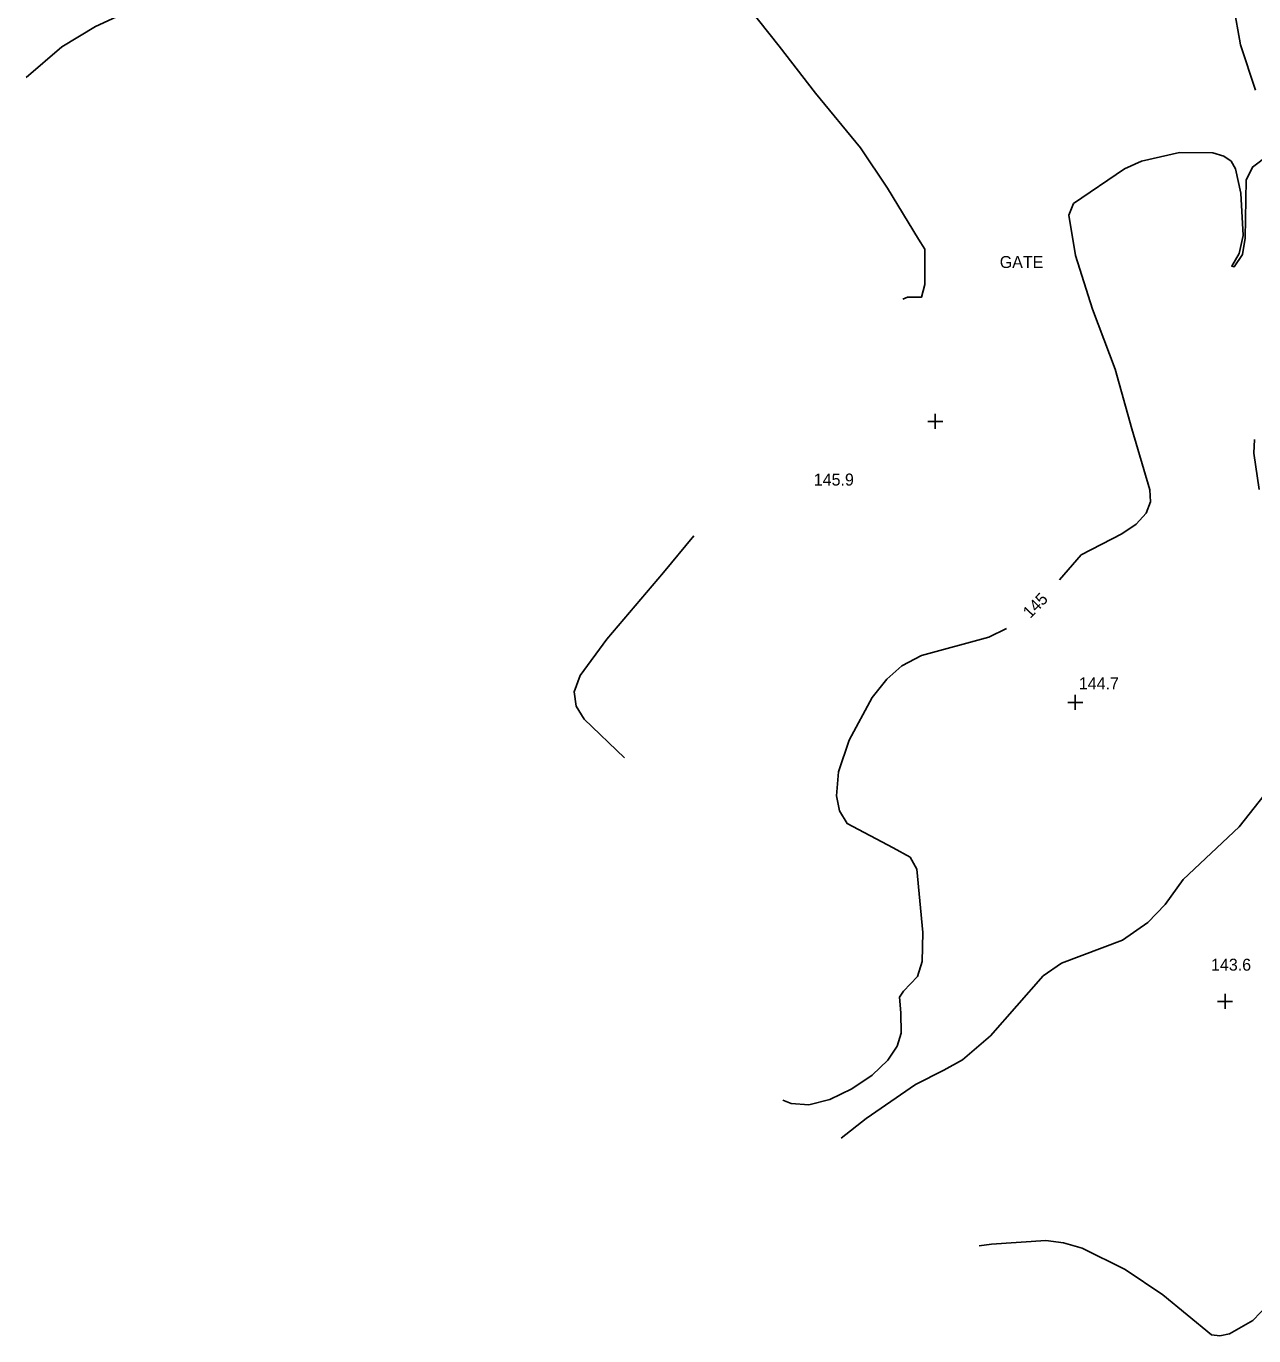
# Model space of a CAD drawing. Extents: x 1475150 to 2003689, y 770235 to 1112803.
# Drawn here: x 2000499.7 to 2000704.8, y 773169.2 to 773388 of the extents above; entities that cross this region are included whole.
import ezdxf

# ---------------------------------------------------------------- set-up
doc = ezdxf.new("R2010")
doc.units = 0
for name, color, linetype in [('RD_DTM_Major1', 7, 'Continuous'), ('RD_DTM_Major1_Lbl', 7, 'Continuous'), ('RD_DTM_Minor1', 7, 'Continuous'), ('RD_DTM_Spot_Elev', 7, 'Continuous'), ('RD_TX_Misc1', 7, 'Continuous')]:
    doc.layers.add(name, color=color, linetype=linetype)

msp = doc.modelspace()

# ---------------------------------------------------------------- linework, layer by layer
at = {"layer": 'RD_DTM_Major1'}
for points in [[(2000705.14, 773377.31), (2000702.59, 773384.88), (2000701.44, 773391.45), (2000701.5, 773391.94), (2000699.64, 773396.47), (2000696.55, 773402.64), (2000692.45, 773404.42), (2000684.77, 773413.19), (2000676.69, 773422.15), (2000669.9, 773431), (2000663.35, 773440.44), (2000659.41, 773446.84), (2000651.72, 773456.99), (2000645.49, 773466.43), (2000644.78, 773467.94), (2000651.37, 773460.88), (2000657.94, 773454.69), (2000665.19, 773448.22), (2000677.03, 773437.38), (2000688.27, 773427.04), (2000699.21, 773417.42), (2000702.1, 773418.42), (2000706.28, 773417.44)], [(2000672.38, 773295.48), (2000675.99, 773299.66), (2000682.8, 773303.17), (2000685.16, 773304.8), (2000686.87, 773306.6), (2000687.58, 773308.5), (2000687.46, 773310.53), (2000684.47, 773320.74), (2000681.69, 773330.68), (2000677.88, 773340.71), (2000675.03, 773349.68), (2000673.94, 773356.43), (2000674.71, 773358.35), (2000683.21, 773364.16), (2000686.05, 773365.46), (2000692.44, 773366.88), (2000697.99, 773366.81), (2000699.81, 773366.3), (2000701.03, 773365.43), (2000701.8, 773364.14), (2000702.68, 773360.09), (2000703.07, 773353.04), (2000702.39, 773350.01), (2000701.15, 773347.87), (2000701.57, 773347.79), (2000702.93, 773349.85), (2000703.37, 773352.6), (2000703.54, 773362.29), (2000704.61, 773364.46), (2000707.35, 773366.5)], [(2000626.16, 773208.53), (2000627.55, 773207.98), (2000630.51, 773207.78), (2000634, 773208.67), (2000637.67, 773210.43), (2000641.05, 773212.72), (2000643.68, 773215.2), (2000645.25, 773217.57), (2000645.92, 773219.73), (2000645.85, 773223.15), (2000645.65, 773225.78), (2000646.28, 773226.78), (2000648.65, 773229.19), (2000649.43, 773231.7), (2000649.53, 773236.55), (2000648.51, 773247.13), (2000647.43, 773249.12), (2000644.58, 773250.71), (2000636.89, 773254.76), (2000635.62, 773256.86), (2000635.09, 773259.4), (2000635.44, 773263.41), (2000637.24, 773268.67), (2000641.06, 773275.84), (2000643.5, 773278.89), (2000646.03, 773281.1), (2000649.29, 773282.82), (2000660.57, 773285.92), (2000663.53, 773287.35)]]:
    msp.add_lwpolyline(points, dxfattribs=at)
at = {"layer": 'RD_DTM_Minor1'}
for points in [[(2000499.72, 773379.42), (2000505.7, 773384.57), (2000511.32, 773387.93), (2000518.41, 773391.23)], [(2000646.18, 773342.38), (2000646.95, 773342.74), (2000649.33, 773342.73), (2000649.85, 773344.85), (2000649.87, 773350.73), (2000648.8, 773352.43), (2000643.61, 773360.94), (2000639.12, 773367.69), (2000631.63, 773376.83), (2000625.53, 773384.66), (2000620.36, 773391.16)], [(2000705.75, 773310.56), (2000704.82, 773316.67), (2000704.93, 773318.92)], [(2000599.69, 773265.74), (2000592.97, 773272.21), (2000591.59, 773274.39), (2000591.28, 773276.77), (2000592.26, 773279.49), (2000596.76, 773285.55), (2000606.22, 773296.7), (2000611.29, 773302.83)], [(2000635.87, 773202.2), (2000640.09, 773205.47), (2000648.3, 773211.17), (2000653.06, 773213.55), (2000656.17, 773215.26), (2000660.83, 773219.31), (2000669.67, 773229.29), (2000672.71, 773231.45), (2000682.89, 773235.25), (2000687.14, 773238.23), (2000690.05, 773241.26), (2000693.02, 773245.41), (2000702.38, 773254.19), (2000710.74, 773264.78)], [(2000658.94, 773184.22), (2000661.01, 773184.5), (2000670.11, 773185.08), (2000673.02, 773184.73), (2000676.18, 773183.83), (2000683.33, 773180.27), (2000689.66, 773176.01), (2000697.76, 773169.34), (2000699.15, 773169.17), (2000700.78, 773169.48), (2000704.69, 773171.74), (2000708.5, 773175.76)]]:
    msp.add_lwpolyline(points, dxfattribs=at)
at = {"layer": 'RD_DTM_Spot_Elev'}
for p, q in [((2000651.62, 773320.71), (2000651.62, 773323.21)), ((2000650.37, 773321.96), (2000652.87, 773321.96)), ((2000673.75, 773275), (2000676.25, 773275)), ((2000675, 773273.75), (2000675, 773276.25)), ((2000698.8, 773225.04), (2000701.3, 773225.04)), ((2000700.05, 773223.79), (2000700.05, 773226.29))]:
    msp.add_line(p, q, dxfattribs=at)

# ---------------------------------------------------------------- texts
at = {"layer": 'RD_DTM_Major1_Lbl'}
msp.add_text('145', height=2, rotation=45.6259, dxfattribs=at).set_placement((2000667.47, 773288.92))
at = {"layer": 'RD_DTM_Spot_Elev'}
for s, p in [('145.9', (2000631.32, 773311.24)), ('144.7', (2000675.6, 773277.17)), ('143.6', (2000697.69, 773230.18))]:
    msp.add_text(s, height=2, dxfattribs=at).set_placement(p)
at = {"layer": 'RD_TX_Misc1'}
msp.add_text('GATE', height=2, dxfattribs=at).set_placement((2000662.39, 773347.59))

doc.saveas('drawing.dxf')
